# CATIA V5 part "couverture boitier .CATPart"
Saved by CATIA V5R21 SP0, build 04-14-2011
Part number: couverture boitier 
Bounding box of the stored display mesh (mm): x -18.5 to 18.5, y -25 to 25, z -6 to 0
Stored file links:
  C:\Users\pc\Desktop\PFA SIMULATION\couverture boitier .CATPart
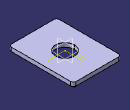
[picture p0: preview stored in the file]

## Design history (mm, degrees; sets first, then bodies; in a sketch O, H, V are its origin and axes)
Body1 (main body)
  Sketch1 on xy-plane, origin (0, 0, 0), H (1, 0, 0), V (0, 1, 0)
    line L1 (-18.5, 25) -> (18.5, 25)
    line L2 (18.5, 25) -> (18.5, -25)
    line L3 (18.5, -25) -> (-18.5, -25)
    line L4 (-18.5, -25) -> (-18.5, 25)
    circle A1 centre (0, 0) radius 7.5
    length L2 = 50
    distance L3 H = 25
    length L1 = 37
    angle L4 L1 = 90
    angle L1 L2 = 90
    distance L4 V = 18.5
    radius A1 = 7.5
  Pad1: profile Sketch1, direction (0, 0, -1), length 3
  Fillet1: radius 2, on edge [face of Pad1 from Sketch1.L2 | face of Pad1 from Sketch1.L1]
  Fillet2: radius 2, on edge [face of Pad1 from Sketch1.L3 | face of Pad1 from Sketch1.L2]
  Fillet3: radius 2, on edge [face of Pad1 from Sketch1.L1 | face of Pad1 from Sketch1.L4]
  Fillet4: radius 2, on edge [face of Pad1 from Sketch1.L4 | face of Pad1 from Sketch1.L3]
  Sketch2 on end face of Pad1, origin (0, 0, -3), H (1, 0, 0), V (0, -1, 0)
    line L1 (-12.6805, 22) -> (12.6805, 22)
    line L2 (15.5, 19.0054) -> (15.5, -20)
    line L3 (14.7361, -22) -> (-12.6805, -22)
    line L4 (-15.5, -19.0054) -> (-15.5, 19.0054)
    reference projected line E1 (18.5, -25) -> (-18.5, -25) from edge [end face of Pad1 | face of Pad1 from Sketch1.L1]
    reference projected line E2 (-18.5, 25) -> (18.5, 25) from edge [end face of Pad1 | face of Pad1 from Sketch1.L3]
    reference projected line E3 (18.5, 25) -> (18.5, -25) from edge [end face of Pad1 | face of Pad1 from Sketch1.L2]
    reference projected line E4 (-18.5, -25) -> (-18.5, 25) from edge [end face of Pad1 | face of Pad1 from Sketch1.L4]
    arc A1 centre (12.5, 19.0054) radius 3 from (12.6805, 22) to (15.5, 19.0054) cw
    arc A2 centre (12.5, -20) radius 3 from (14.7361, -22) to (15.5, -20) ccw
    arc A3 centre (-12.5, 19.0054) radius 3 from (-12.6805, 22) to (-15.5, 19.0054) ccw
    arc A4 centre (-12.5, -19.0054) radius 3 from (-12.6805, -22) to (-15.5, -19.0054) cw
    line L5 (-12.5, 20.0124) -> (12.5, 20)
    line L6 (12.5, 20) -> (12.5, -20)
    line L7 (12.5, -20) -> (-12.5198, -20)
    line L8 (-12.5198, -20) -> (-12.5, 20.0124)
    distance L3 E1 = 3
    distance L1 E2 = 3
    distance L2 E3 = 3
    distance L4 E4 = 3
    radius A1 = 3
    radius A2 = 3
    radius A3 = 3
    radius A4 = 3
    length L5 = 25
    length L6 = 40
    distance L6 V = 12.5
    distance L7 H = 20
  Pocket1: profile Sketch2, direction (0, 0, 1), length 5
  Pad2: profile Sketch2, direction (0, 0, -1), length 3
  Pad3: profile Sketch2, direction (0, 0, -1), length 3, mirrored extent
  Sketch3 on start face of Pad1, origin (0, 0, 0), H (1, 0, 0), V (0, 1, 0)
